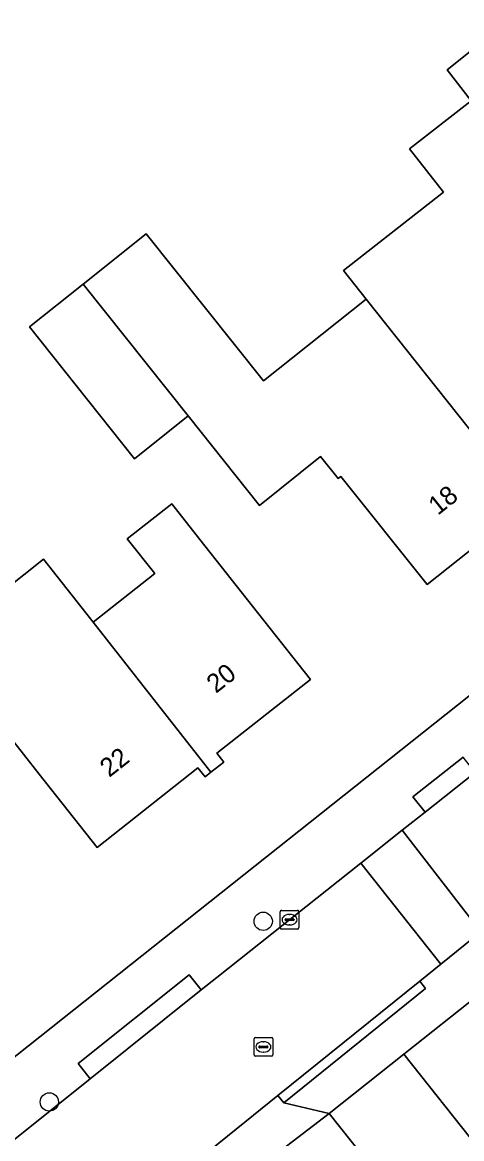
# Model space of a CAD drawing. Extents: x 159499 to 160349, y 382524 to 383273.
# Drawn here: x 159941.1 to 159964.6, y 383112.7 to 383172.4 of the extents above; entities that cross this region are included whole.
import ezdxf

# ---------------------------------------------------------------- set-up
doc = ezdxf.new("R2010")
doc.units = 0
for name, color, linetype in [('IMGEO_Boom', 7, 'Continuous'), ('IMGEO_Erf', 7, 'Continuous'), ('IMGEO_Kolk', 7, 'Continuous'), ('IMGEO_Pand', 7, 'Continuous'), ('IMGEO_Pand_nummerreeks', 7, 'Continuous'), ('IMGEO_Rijbaan_lokaal_open', 7, 'Continuous'), ('IMGEO_Rioolput', 7, 'Continuous'), ('IMGEO_Voetpad_open', 7, 'Continuous')]:
    doc.layers.add(name, color=color, linetype=linetype)

msp = doc.modelspace()

# ---------------------------------------------------------------- linework, layer by layer
at = {"layer": 'IMGEO_Boom'}
for centre in [(159953.976, 383124.302), (159942.522, 383114.632)]:
    msp.add_circle(centre, 0.489, dxfattribs=at)
at = {"layer": 'IMGEO_Erf'}
for points in [[(159968.19, 383146.654), (159962.752, 383142.321), (159958.134, 383148.116), (159957.986, 383147.998), (159957.052, 383149.172), (159953.776, 383146.561), (159949.956, 383151.355), (159947.079, 383149.062), (159941.458, 383156.117), (159944.335, 383158.41), (159947.715, 383161.103), (159953.991, 383153.228), (159959.487, 383157.608), (159958.267, 383159.133), (159963.63, 383163.326), (159961.817, 383165.646), (159965.112, 383168.222), (159963.819, 383169.871), (159967.029, 383172.422)], [(159838.776, 383036.162), (160000, 383164.155)], [(159939.12, 383141.236), (159942.212, 383143.679), (159944.477, 383140.812), (159944.875, 383140.308), (159948.168, 383142.91), (159946.696, 383144.773), (159949.077, 383146.654), (159950.584, 383144.744), (159953.402, 383141.175), (159956.502, 383137.251), (159951.497, 383133.297), (159951.868, 383132.826), (159951.175, 383132.278), (159950.867, 383132.035), (159950.482, 383132.522), (159945.081, 383128.255), (159941.981, 383132.179), (159939.442, 383135.393)]]:
    msp.add_lwpolyline(points, dxfattribs=at)
at = {"layer": 'IMGEO_Kolk'}
for p, q in [((159954.884, 383123.961), (159954.884, 383124.813)), ((159954.959, 383124.887), (159955.811, 383124.887)), ((159955.885, 383124.813), (159955.885, 383123.961)), ((159955.143, 383124.381), (159955.143, 383124.393)), ((159955.581, 383124.344), (159955.183, 383124.344)), ((159955.186, 383124.43), (159955.584, 383124.43)), ((159955.372, 383124.667), (159955.397, 383124.667)), ((159955.627, 383124.393), (159955.627, 383124.381)), ((159955.811, 383123.887), (159954.959, 383123.887)), ((159955.395, 383124.107), (159955.37, 383124.107))]:
    msp.add_line(p, q, dxfattribs=at)
for points in [[(159954.884, 383123.961), (159954.884, 383124.813)], [(159954.959, 383124.887), (159955.811, 383124.887)], [(159955.885, 383124.813), (159955.885, 383123.961)], [(159955.811, 383123.887), (159954.959, 383123.887)]]:
    msp.add_lwpolyline(points, dxfattribs=at)
for centre, radius, start, end in [((159954.961, 383124.811), 0.0765, 91.55205, 178.44795), ((159954.961, 383124.811), 0.0765, 91.55205, 178.44795), ((159955.809, 383124.811), 0.0765, 1.55205, 88.44795), ((159955.809, 383124.811), 0.0765, 1.55205, 88.44795), ((159955.183, 383124.39), 0.0403, 85.87752, 175.75265), ((159955.18, 383124.38), 0.0366, 178.93798, 274.71019), ((159955.584, 383124.387), 0.043, 264.86636, 352.45326), ((159955.588, 383124.392), 0.0386, 1.73085, 96.63898), ((159954.961, 383123.963), 0.0765, 181.55205, 268.44795), ((159954.961, 383123.963), 0.0765, 181.55205, 268.44795), ((159955.809, 383123.963), 0.0765, 271.55205, 358.44795), ((159955.809, 383123.963), 0.0765, 271.55205, 358.44795)]:
    msp.add_arc(centre, radius, start, end, dxfattribs=at)
for centre, major_axis, ratio, start_param, end_param in [((159955.371, 383124.387), (-0.387, 0.002), 0.722429, 4.712389, 7.853982), ((159955.396, 383124.387), (-0.39, 0.002), 0.717154, 1.570796, 4.712389)]:
    msp.add_ellipse(centre, major_axis=major_axis, ratio=ratio, start_param=start_param, end_param=end_param, dxfattribs=at)
at = {"layer": 'IMGEO_Pand'}
for points in [[(159978.922, 383168.551), (159978.198, 383169.471), (159977.473, 383170.391), (159972.052, 383166.099), (159967.029, 383172.422), (159963.819, 383169.871), (159965.112, 383168.222), (159969.521, 383162.599), (159972.927, 383158.28), (159976.071, 383160.769), (159979.932, 383155.892), (159980.279, 383156.167), (159979.672, 383156.934), (159984.685, 383160.902), (159985.28, 383160.15), (159985.462, 383160.294)], [(159966.366, 383160.212), (159969.521, 383162.599), (159965.112, 383168.222), (159961.817, 383165.646), (159963.63, 383163.326), (159958.267, 383159.133), (159959.487, 383157.608), (159968.19, 383146.654), (159973.675, 383151.025), (159970.559, 383154.936)], [(159968.19, 383146.654), (159959.487, 383157.608), (159953.991, 383153.228), (159947.715, 383161.103), (159944.335, 383158.41), (159949.956, 383151.355), (159953.776, 383146.561), (159957.052, 383149.172), (159957.986, 383147.998), (159958.134, 383148.116), (159962.752, 383142.321)], [(159944.335, 383158.41), (159941.458, 383156.117), (159947.079, 383149.062), (159949.956, 383151.355)], [(159951.175, 383132.278), (159951.868, 383132.826), (159951.497, 383133.297), (159956.502, 383137.251), (159953.402, 383141.175), (159950.584, 383144.744), (159949.077, 383146.654), (159946.696, 383144.773), (159948.168, 383142.91), (159944.875, 383140.308)], [(159944.875, 383140.308), (159944.477, 383140.812), (159942.212, 383143.679), (159939.12, 383141.236), (159936.476, 383139.148), (159936.998, 383138.487), (159937.246, 383138.173), (159938.697, 383136.337), (159939.442, 383135.393), (159941.981, 383132.179), (159945.081, 383128.255), (159950.482, 383132.522), (159950.867, 383132.035), (159951.175, 383132.278)]]:
    msp.add_lwpolyline(points, close=True, dxfattribs=at)
at = {"layer": 'IMGEO_Rijbaan_lokaal_open'}
for points in [[(160007.337, 383165.518), (159985.41, 383148.209), (159982.548, 383145.937), (159982.197, 383145.658), (159979.79, 383143.748), (159968.366, 383134.687), (159965.633, 383132.52), (159965.323, 383132.274), (159962.64, 383130.146), (159961.424, 383129.181), (159965.635, 383123.738), (160005.521, 383155.177), (160009.599, 383158.345)], [(159965.56, 383120.401), (159961.505, 383117.191), (159966.858, 383110.439), (159969.339, 383112.369), (160000, 383136.696)], [(160000, 383068.637), (159989.829, 383081.465), (159986.263, 383085.963), (159980.273, 383093.518), (159973.467, 383102.103), (159966.858, 383110.439), (159961.505, 383117.191), (159957.5, 383114.019), (159962.836, 383107.311), (159995.46, 383066.299)], [(159961.699, 383106.426), (159962.836, 383107.311), (159957.5, 383114.019), (159954.685, 383111.851)]]:
    msp.add_lwpolyline(points, dxfattribs=at)
for points in [[(159965.635, 383123.738), (159961.424, 383129.181), (159959.2, 383127.414), (159963.491, 383122.013)], [(159959.2, 383127.414), (159951.49, 383121.291), (159950.655, 383120.624), (159944.715, 383115.876), (159925.553, 383100.562), (159923.387, 383098.831), (159920.045, 383096.187), (159910.271, 383088.453), (159907.499, 383086.26), (159900.872, 383081.016), (159905.174, 383075.589), (159911.357, 383080.502), (159950.297, 383111.374), (159954.759, 383114.972), (159962.358, 383121.1), (159963.491, 383122.013)]]:
    msp.add_lwpolyline(points, close=True, dxfattribs=at)
at = {"layer": 'IMGEO_Rioolput'}
for p, q in [((159953.488, 383117.15), (159953.488, 383118.002)), ((159953.563, 383118.076), (159954.415, 383118.076)), ((159953.747, 383117.57), (159953.747, 383117.582)), ((159953.79, 383117.619), (159954.188, 383117.619)), ((159953.976, 383117.856), (159954.001, 383117.856)), ((159954.231, 383117.582), (159954.231, 383117.57)), ((159954.489, 383118.002), (159954.489, 383117.15)), ((159954.415, 383117.076), (159953.563, 383117.076)), ((159954.185, 383117.533), (159953.787, 383117.533)), ((159953.999, 383117.296), (159953.974, 383117.296))]:
    msp.add_line(p, q, dxfattribs=at)
for points in [[(159953.488, 383117.15), (159953.488, 383118.002)], [(159953.563, 383118.076), (159954.415, 383118.076)], [(159954.489, 383118.002), (159954.489, 383117.15)], [(159954.415, 383117.076), (159953.563, 383117.076)]]:
    msp.add_lwpolyline(points, dxfattribs=at)
for centre, radius, start, end in [((159953.565, 383118), 0.0765, 91.55205, 178.44795), ((159953.565, 383118), 0.0765, 91.55205, 178.44795), ((159953.787, 383117.579), 0.0403, 85.87752, 175.75265), ((159954.192, 383117.581), 0.0386, 1.73085, 96.63898), ((159954.413, 383118), 0.0765, 1.55205, 88.44795), ((159954.413, 383118), 0.0765, 1.55205, 88.44795), ((159953.565, 383117.152), 0.0765, 181.55205, 268.44795), ((159953.565, 383117.152), 0.0765, 181.55205, 268.44795), ((159953.784, 383117.569), 0.0366, 178.93798, 274.71019), ((159954.188, 383117.576), 0.043, 264.86636, 352.45326), ((159954.413, 383117.152), 0.0765, 271.55205, 358.44795), ((159954.413, 383117.152), 0.0765, 271.55205, 358.44795)]:
    msp.add_arc(centre, radius, start, end, dxfattribs=at)
for centre, major_axis, ratio, start_param, end_param in [((159953.975, 383117.576), (-0.387, 0.002), 0.722429, 4.712389, 7.853982), ((159954, 383117.576), (-0.39, 0.002), 0.717154, 1.570796, 4.712389)]:
    msp.add_ellipse(centre, major_axis=major_axis, ratio=ratio, start_param=start_param, end_param=end_param, dxfattribs=at)
at = {"layer": 'IMGEO_Voetpad_open'}
for points in [[(160003.86, 383167.245), (160000, 383164.155), (159838.776, 383036.162), (159834.352, 383032.405), (159830.825, 383029.654), (159830.707, 383026.63), (159837.797, 383032.248), (159838.443, 383031.433), (159841.883, 383034.159), (159859.981, 383048.564)], [(159965.635, 383123.738), (159963.491, 383122.013), (159962.358, 383121.1), (159962.671, 383120.711), (159955.072, 383114.583), (159957.5, 383114.019), (159961.505, 383117.191), (159965.56, 383120.401), (159986.191, 383136.82)], [(159925.553, 383100.562), (159944.715, 383115.876), (159944.066, 383116.688), (159950.006, 383121.436), (159950.655, 383120.624), (159951.49, 383121.291), (159959.2, 383127.414), (159961.424, 383129.181), (159962.64, 383130.146), (159961.994, 383130.961), (159964.677, 383133.089)], [(159905.827, 383073.006), (159906.787, 383073.771), (159931.545, 383093.463), (159934.146, 383090.179), (159936.037, 383091.678), (159933.423, 383094.963), (159939.635, 383099.886), (159954.362, 383111.559), (159954.685, 383111.851), (159957.5, 383114.019), (159955.072, 383114.583), (159954.759, 383114.972), (159950.297, 383111.374)]]:
    msp.add_lwpolyline(points, dxfattribs=at)
for points in [[(159965.323, 383132.274), (159964.677, 383133.089), (159961.994, 383130.961), (159962.64, 383130.146)], [(159944.715, 383115.876), (159950.655, 383120.624), (159950.006, 383121.436), (159944.066, 383116.688)], [(159962.358, 383121.1), (159954.759, 383114.972), (159955.072, 383114.583), (159962.671, 383120.711)]]:
    msp.add_lwpolyline(points, close=True, dxfattribs=at)

# ---------------------------------------------------------------- texts
at = {"layer": 'IMGEO_Pand_nummerreeks'}
for s, rotation, p in [('18', 38.54785, (159963.328, 383146.002)), ('20', 38.28565, (159951.446, 383136.47)), ('22', 38.16472, (159945.733, 383131.973))]:
    msp.add_text(s, height=1, rotation=rotation, dxfattribs=at).set_placement(p)

doc.saveas('drawing.dxf')
